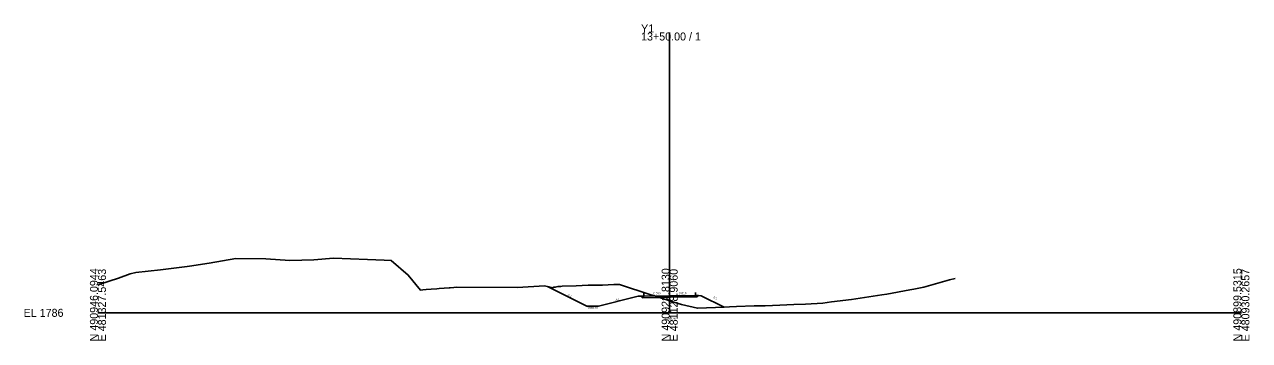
# Model space of a CAD drawing. Extents: x -26 to 403, y -10 to 6561.
# Drawn here: x -25.7 to 402.8, y 3490.3 to 3601 of the extents above; entities that cross this region are included whole.
import ezdxf

# ---------------------------------------------------------------- set-up
doc = ezdxf.new("R2010")
doc.units = 0
for name, color, linetype in [('Exist Cross Section Cell', 7, 'Continuous'), ('Exist XS Center Line Elevation Label', 7, 'Continuous'), ('Exist XS Ground Line', 7, 'Continuous'), ('Prop Road Sect_ Boring - Header (ID Tx)', 7, 'Continuous'), ('Prop Road Sect_ Material - Tx (Composite Desc)', 7, 'Continuous'), ('Prop XS Ditch Slope Text', 7, 'Continuous'), ('Prop XS Ditch Standard Text', 7, 'Continuous'), ('Prop XS EOT Tick Mark', 7, 'Continuous'), ('Prop XS Finish Grade', 7, 'Continuous'), ('Prop XS Finish Grade Earthwork', 7, 'Continuous'), ('Prop XS Finish Grade Pavement', 7, 'Continuous'), ('Prop XS Pvmt Edge Slope', 7, 'Continuous'), ('Prop XS SE Text', 7, 'Continuous'), ('Prop XS Side Slope Text', 7, 'Continuous'), ('Prop XS Subgrade Earthwork', 7, 'Continuous')]:
    doc.layers.add(name, color=color, linetype=linetype)

msp = doc.modelspace()

# ---------------------------------------------------------------- linework, layer by layer
at = {"layer": 'Exist Cross Section Cell'}
for p, q in [((200, 3500), (200, 3598.16)), ((0, 3500), (200, 3500)), ((200, 3500), (400, 3500))]:
    msp.add_line(p, q, dxfattribs=at)
at = {"layer": 'Exist XS Ground Line'}
msp.add_lwpolyline([(0, 3509.57), (0.62, 3510.04), (7.16, 3512.18), (11.29, 3513.64), (13.2, 3514.12), (21.92, 3515.02), (24.7, 3515.38), (31.23, 3516.22), (31.99, 3516.32), (38.85, 3517.4), (48.18, 3519.02), (58.78, 3518.95), (67.18, 3518.28), (75.52, 3518.53), (82.42, 3519.15), (94.33, 3518.66), (100.17, 3518.39), (102.55, 3518.33), (108.55, 3513.23), (112.78, 3507.99), (113.6, 3508.05), (114.87, 3508.15), (116.62, 3508.28), (118.53, 3508.43), (119.37, 3508.5), (121.07, 3508.63), (122.87, 3508.77), (123.2, 3508.79), (124.55, 3508.9), (125.38, 3508.96), (146.78, 3508.83), (156.19, 3509.43), (159, 3508.81), (159.47, 3508.93), (159.96, 3508.95), (160.91, 3509.21), (161.49, 3509.24), (161.92, 3509.27), (162.42, 3509.3), (167.32, 3509.44), (171.44, 3509.68), (176.55, 3509.72), (180.45, 3509.94), (181.09, 3509.92), (181.62, 3509.9), (182.07, 3509.89), (182.46, 3509.88), (193.47, 3506.3), (196.28, 3505.43), (197.86, 3504.93), (198.97, 3504.58), (200, 3504.26), (204.11, 3502.96), (209.68, 3501.6), (216.02, 3501.83), (223.33, 3502.19), (229.53, 3502.41), (233.4, 3502.51), (238.55, 3502.66), (243.47, 3502.87), (247.56, 3503), (253.54, 3503.39), (256.57, 3503.8), (263.61, 3504.72), (274.24, 3506.35), (276.02, 3506.55), (284.06, 3508.11), (285.37, 3508.25), (288.96, 3509.02), (297.95, 3511.6), (299.86, 3512)], dxfattribs=at)
at = {"layer": 'Prop Road Sect_ Boring - Header (ID Tx)'}
for points in [[(190.45, 3505.31), (189.94, 3505.81), (191, 3505.86)], [(210.03, 3506.05), (209.53, 3505.55), (209, 3506.09)]]:
    msp.add_lwpolyline(points, close=True, dxfattribs=at)
at = {"layer": 'Prop Road Sect_ Material - Tx (Composite Desc)'}
for points in [[(171.06, 3502.29), (157.24, 3509.2), (159, 3508.81), (159.47, 3508.93), (159.96, 3508.95), (160.91, 3509.21), (161.49, 3509.24), (161.92, 3509.27), (162.42, 3509.3), (167.32, 3509.44), (171.44, 3509.68), (176.55, 3509.72), (180.45, 3509.94), (181.09, 3509.92), (181.62, 3509.9), (182.07, 3509.89), (182.46, 3509.88), (193.47, 3506.3), (196.28, 3505.43), (196.41, 3505.38), (190.45, 3505.31), (189.94, 3505.81), (189, 3505.78), (175.06, 3502.29)], [(210.03, 3506.05), (211, 3506.01), (219.05, 3501.98), (216.02, 3501.83), (209.68, 3501.6), (204.11, 3502.96), (200, 3504.26), (198.97, 3504.58), (197.86, 3504.93), (196.41, 3505.38), (200.01, 3505.43), (209.53, 3505.55)]]:
    msp.add_lwpolyline(points, close=True, dxfattribs=at)
at = {"layer": 'Prop XS EOT Tick Mark'}
for p, q in [((191, 3505.86), (191, 3506.86)), ((209, 3506.09), (209, 3507.09))]:
    msp.add_line(p, q, dxfattribs=at)
at = {"layer": 'Prop XS Finish Grade'}
for p, q in [((191, 3505.86), (189.94, 3505.81)), ((209, 3506.09), (210.03, 3506.05))]:
    msp.add_line(p, q, dxfattribs=at)
at = {"layer": 'Prop XS Finish Grade Earthwork'}
for p, q in [((171.06, 3502.29), (157.24, 3509.2)), ((189, 3505.78), (175.06, 3502.29)), ((189, 3505.78), (189.94, 3505.81)), ((210.03, 3506.05), (211, 3506.01)), ((211, 3506.01), (219.05, 3501.98)), ((175.06, 3502.29), (171.06, 3502.29))]:
    msp.add_line(p, q, dxfattribs=at)
at = {"layer": 'Prop XS Finish Grade Pavement'}
for p, q in [((191, 3505.86), (200, 3505.97)), ((200, 3505.97), (209, 3506.09))]:
    msp.add_line(p, q, dxfattribs=at)
at = {"layer": 'Prop XS Pvmt Edge Slope'}
for p, q in [((191, 3505.86), (190.45, 3505.31)), ((209, 3506.09), (209.53, 3505.55))]:
    msp.add_line(p, q, dxfattribs=at)
at = {"layer": 'Prop XS Subgrade Earthwork'}
for p, q in [((190.45, 3505.31), (189.94, 3505.81)), ((190.45, 3505.31), (200.01, 3505.43)), ((200.01, 3505.43), (209.53, 3505.55)), ((210.03, 3506.05), (209.53, 3505.55))]:
    msp.add_line(p, q, dxfattribs=at)

# ---------------------------------------------------------------- texts
at = {"layer": 'Exist Cross Section Cell'}
for s, p in [('Y1', (190, 3598.16)), ('13+50.00 / 1', (190, 3595.36)), ('EL 1786', (-26, 3498.6))]:
    msp.add_text(s, height=2.8, dxfattribs=at).set_placement(p)
for s, p in [('N 490946.0944', (0, 3490)), ('E 481327.5463', (2.8, 3490)), ('N 490922.8130', (200, 3490)), ('E 481128.9060', (202.8, 3490)), ('N 490899.5315', (400, 3490)), ('E 480930.2657', (402.8, 3490))]:
    msp.add_text(s, height=2.8, rotation=90, dxfattribs=at).set_placement(p)
at = {"layer": 'Exist XS Center Line Elevation Label'}
msp.add_text('1790.26', height=0.75, dxfattribs=at).set_placement((198.32, 3497.58))
at = {"layer": 'Prop XS Ditch Slope Text'}
msp.add_text('4:1', height=0.75, rotation=14.0362, dxfattribs=at).set_placement((181.17, 3504.12))
at = {"layer": 'Prop XS Ditch Standard Text'}
msp.add_text('1788.29', height=0.75, dxfattribs=at).set_placement((171.17, 3501.3))
at = {"layer": 'Prop XS SE Text'}
for p in [(194.27, 3506.4), (203.27, 3506.51)]:
    msp.add_text('0.013', height=0.75, rotation=0.741, dxfattribs=at).set_placement(p)
at = {"layer": 'Prop XS Side Slope Text'}
for p in [(164.22, 3506.03), (215.15, 3505.18)]:
    msp.add_text('2:1', height=0.75, rotation=333.4349, dxfattribs=at).set_placement(p)

doc.saveas('drawing.dxf')
